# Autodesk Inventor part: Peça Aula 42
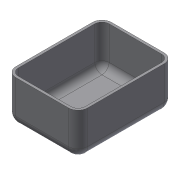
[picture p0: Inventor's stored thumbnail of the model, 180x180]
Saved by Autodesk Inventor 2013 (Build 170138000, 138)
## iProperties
Created: 2013-05
Part Number: Peça Aula 42
Material: Genérico
Document SubType Name: Modeling
Designer: Draw
Density: 1 g/cm^3
Author: Draw
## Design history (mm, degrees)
sketch "Esboço1"
  geometry: L1 (-75, -100)-(75, -100); L2 (75, -100)-(75, 100); L3 (75, 100)-(-75, 100); L4 (-75, 100)-(-75, -100); L5 (-75, -100)-(75, 100); L6 (75, -100)-(-75, 100); 1 further point
  constraints: 12 end point, 2 midpoint, 2 parallel, 1 horizontal, 1 perpendicular
  dimensions: "d0" = 150 distance of L3.end L2.end; "d1" = 200 distance of L2.end L1.end
extrude "Extrusão1" new body sketch "Esboço1" distance "d2" = 90; taper "d3" = 0 deg
fillet "Arredondamento1" dims "d4" = 20
feature "Casca1" dims "d5" = 5
node "Sólido1"
